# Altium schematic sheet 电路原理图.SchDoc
size 419 x 297 mm
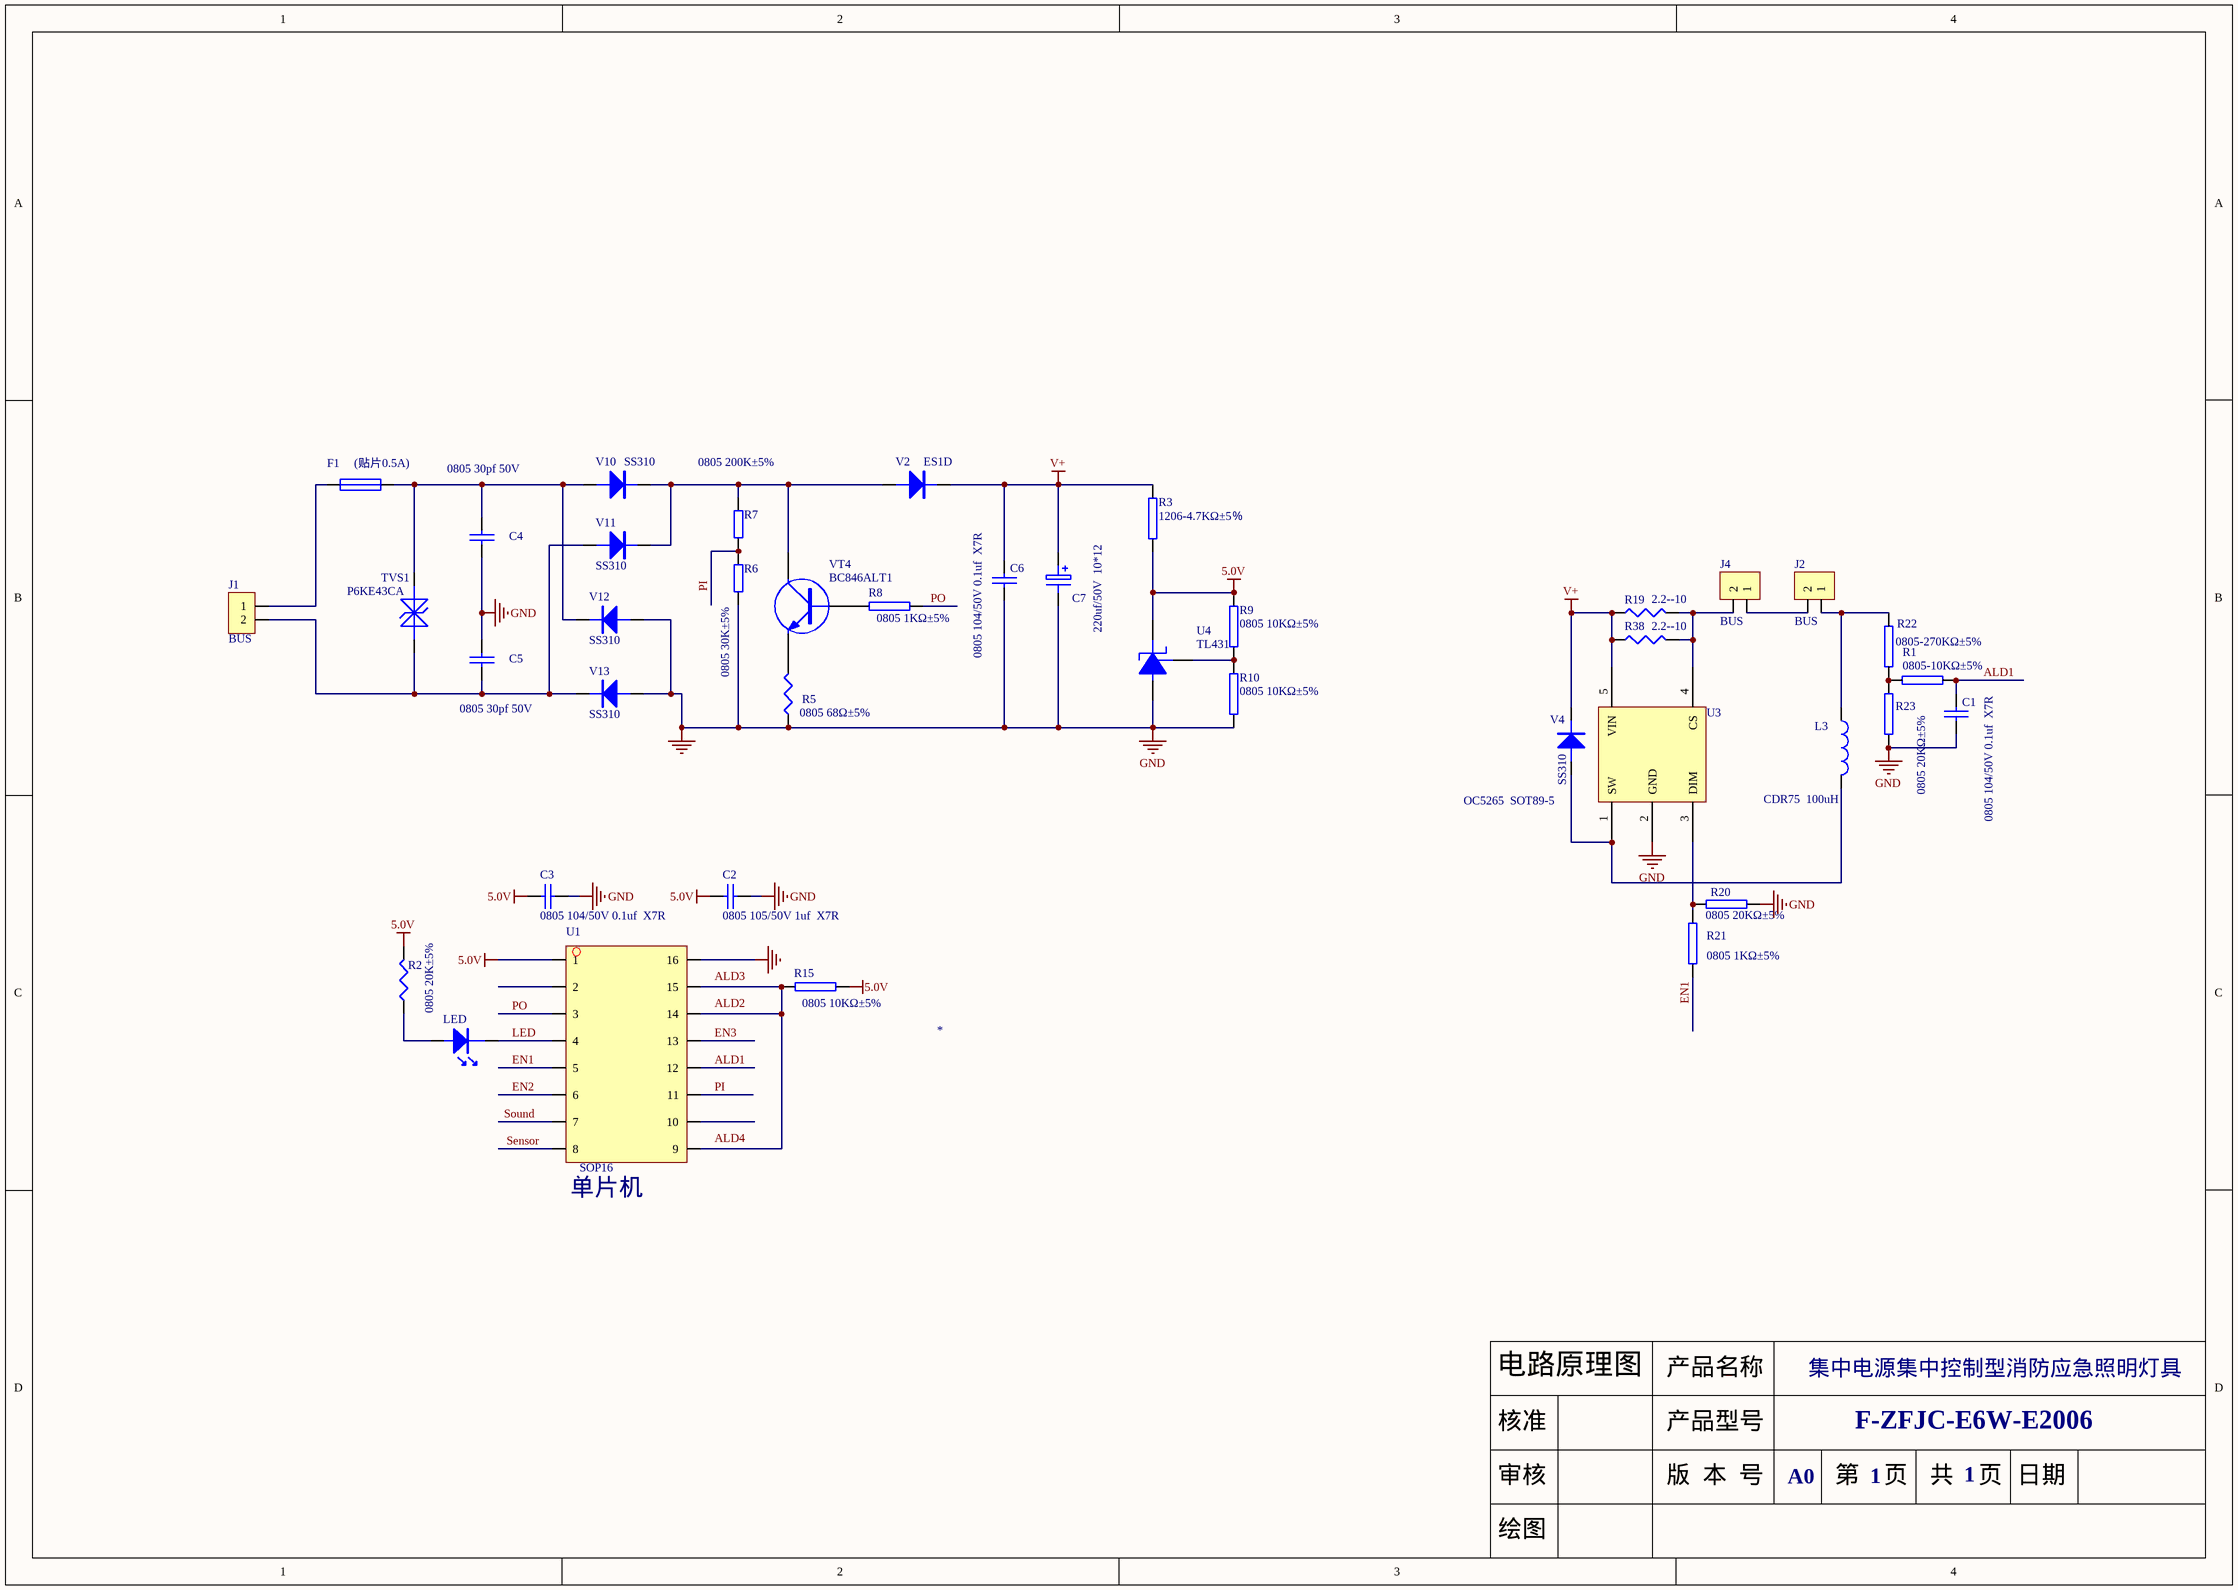
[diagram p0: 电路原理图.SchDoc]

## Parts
C1  0805 104/50V 0.1uf  X7R  [0805-c]
C2  0805 105/50V 1uf  X7R  [0805-c]
C3  0805 104/50V 0.1uf  X7R  [0805-c]
C4  0805 30pf 50V  [0805-c]
C5  0805 30pf 50V  [0805-c]
C6  0805 104/50V 0.1uf  X7R  [0805-c]
C7  220uf/50V  10*12  [CE8-10]
F1  (贴片0.5A)  [贴片保险]
J1  BUS  [TJC-2]
J2  BUS  [TJC-2]
J4  BUS  [TJC-2]
L3  CDR75  100uH  [L8]
LED  (no value)  [led0805]
R1  0805-10KΩ±5%  [0805]
R2  0805 20K±5%  [0805]
R3  1206-4.7KΩ±5％  [1206]
R5  0805 68Ω±5%  [0805]
R6  0805 30K±5%  [0805]
R7  0805 200K±5%  [0805]
R8  0805 1KΩ±5%  [0805]
R9  0805 10KΩ±5%  [0805]
R10  0805 10KΩ±5%  [0805]
R15  0805 10KΩ±5%  [0805]
R19  2.2--10  [1206]
R20  0805 20KΩ±5%  [0805]
R21  0805 1KΩ±5%  [0805]
R22  0805-270KΩ±5%  [0805]
R23  0805 20KΩ±5%  [0805]
R38  2.2--10  [1206]
TVS1  P6KE43CA  [SMT_TVS]
U1  SOP16  [SOP-16b]
U3  OC5265  SOT89-5  [SOT-89-5]
U4  TL431  [SOT23-A2]
V2  ES1D  [VDM7]
V4  SS310  [VDM7]
V10  SS310  [VDM7]
V11  SS310  [VDM7]
V12  SS310  [VDM7]
V13  SS310  [VDM7]
VT4  BC846ALT1  [SOT-23]

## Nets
5.0V: C2.1 C3.1 R2.2 R3.2 R9.2 R15.1 U1.1 U4.2
GND: C1.2 C2.2 C3.2 C4.2 C5.1 C6.2 C7.2 R5.1 R6.1 R10.1 R20.1 R23.1 U1.16 U3.2(GND) U4.3 V12.A V13.A
V+: C6.1 C7.1 R3.1 R19.1 R38.1 U3.5(VIN) V2.K V4.K
ALD1: C1.1 R1.1 U1.12
EN1: R21.1 U1.5
EN2: U1.6
EN3: U1.13
LED: LED.K U1.4
PI: R6.2 R7.1 U1.11
PO: R8.2 U1.3
Sensor: U1.8
Sound: U1.7
NetC4_1: C4.1 F1.2 TVS1.A V10.A V12.K
NetC5_2: C5.2 J1.2 TVS1.K V11.A V13.K
NetF1_1: F1.1 J1.1
NetJ2_1: J2.1 L3.1 R22.2
NetJ2_2: J2.2 J4.1
NetJ4_2: J4.2 R19.2 R38.2 U3.4(CS)
NetL3_2: L3.2 U3.1(SW) V4.A
NetLED_A: LED.A R2.1
NetR1_2: R1.2 R22.1 R23.2
NetR5_2: R5.2 VT4.2(E)
NetR7_2: R7.2 V2.A V10.K V11.K VT4.3(C)
NetR8_1: R8.1 VT4.1(B)
NetR9_1: R9.1 R10.2 U4.1
NetR15_2: R15.2 U1.9 U1.14 U1.15
NetR20_2: R20.2 R21.2 U3.3(DIM)

Not connected (* = marked no-connect by the designer): U1 2 10

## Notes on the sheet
- (near U1) 单片机
- 集中电源集中控制型消防应急照明灯具
- F-ZFJC-E6W-E2006
- A0
- 1
- Labels drawn without touching a wire or pin: ALD2, ALD3, ALD4

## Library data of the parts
C1-C3 C6 = CAP: 料号: 4.1.CTX.004; 型号规格: 104/50V ±10% X7R 5000H RoHS; 名称: 0603封装贴片电容
C4 C5 = CAP: 料号: 4.1.CTX.054; 型号规格: 30PF/50V ±10% X7R 5000H RoHS; 名称: 0603封装贴片电容
C7 = ELECTRO1: 料号: 4.1.C.113; 型号规格: 330UF/50V 10*16 105℃ 误差±20% 5000-10000H 脚长(3.2-3.5mm); 名称: 电解电容
F1 = FUSE1: 料号: 4.3.X.111; 型号规格: 仓 24F系列 快断保险管 2A250V; 名称: 贴片保险管
J1 J2 J4 = CON2
L3 = INDUCTOR: 料号: 4.5.LG.151; 型号规格: CD54-100uH; 名称: 贴片电感
LED = LED: 料号: 4.3.LED.250; 名称: 发光二极管; 型号规格: C0805UG-ES 高亮白发绿贴片 VF:2.8-3.0 IV:250-300 WLD:515-520  IF:30MA
R1 R22 = RES1: 料号: 4.2.RTX.009; 型号规格: 204(200KΩ) ±5%; 名称: 0603封装贴片电阻
R2 = RES1: 料号: 4.2.RTD.246; 型号规格: 15R(15Ω) ±1%RoHS; 名称: 0805封装贴片电阻
R3 = RES2
R5 = RES1: 料号: 4.2.RTD.244; 型号规格: 680(68Ω) ±5%; 名称: 0805封装贴片电阻
R6 = RES: 料号: 4.2.RTD.044; 型号规格: 203(20KΩ) ±5%; 名称: 0805封装贴片电阻
R7 = RES: 料号: 4.2.RTD.130; 型号规格: 274(270KΩ) ±5%; 名称: 0805封装贴片电阻
R8-R10 R15 R21 = RES2: 料号: 4.2.RTX.002; 型号规格: 102(1KΩ) ±5%; 名称: 0603封装贴片电阻
R19 R38 = RES1: 料号: 调试待定; 名称: 1206贴片封装电阻
R20 = RES2: 料号: 4.2.RTX.003; 型号规格: 103(10KΩ) ±5%; 名称: 0603封装贴片电阻
R23 = RES2: 料号: 4.2.RTX.035A; 型号规格: 203(20KΩ) ±1%; 名称: 0603封装贴片电阻
TVS1 = TVS1: 料号: 4.3.DT.064; 型号规格: 瞬态二极管 P6KE43CA  SMT_TVS; 名称: 贴片瞬态二极管
U3 = BP1360: 料号: 新料; 名称: 贴片IC
V2 V4 V10-V13 = DIODE: pin to pad: A>1 K>2; 料号: 4.3.DT.065; 型号规格: SS310 SMA 3A/100V  RoHS; 名称: 贴片肖特基二极
VT4 = NPN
